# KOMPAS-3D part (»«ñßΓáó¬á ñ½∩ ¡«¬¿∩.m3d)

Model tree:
1. Эскиз:1
2. Операция выдавливания:1
     Расстояние 1 = 10
3. Эскиз:2
4. Операция выдавливания:2
     Расстояние 1 = 30
5. Эскиз:3
6. Вырезать элемент выдавливания:1
     Расстояние 1 = 20
7. Скругление:1
     Радиус = 3
8. Скругление:2
     Радиус = 3
9. Эскиз:4
10. Вырезать элемент выдавливания:2
     Расстояние 1 = 20
11. Эскиз:5
12. Вырезать элемент выдавливания:3
     Расстояние 1 = 4; Угол 1 = 30
13. Эскиз:6
14. Вырезать элемент выдавливания:4
     Толщина стенки 1 = 0.1; Расстояние 1 = 4
15. Эскиз:7
16. Вырезать элемент выдавливания:5
     Расстояние 1 = 150
